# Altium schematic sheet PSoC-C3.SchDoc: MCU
size A3; CompanyName: Hitex GmbH; Address1: Greschbachstr. 12; Address2: 76229 Karlsruhe, Germany; Address3: www.hitex.com; DocumentNumber: 2; SheetNumber: 2; SheetTotal: 8; PageSetup: Record=PageOptions¦CenterHorizontal=True¦CenterVertical=True¦PrintScale=1.04¦XCorrection=1.00¦YCorrection=1.00¦PrintKind=0¦BorderSize=5000000¦LeftOffset=0¦BottomOffset=0¦Orientation=2¦PaperLength=1000¦PaperWidth=1000¦Scale=100¦PaperSource=7¦PrintQuality=1200¦MediaType=1¦DitherType=10¦PaperKind=A3¦PrintScaleMode=1
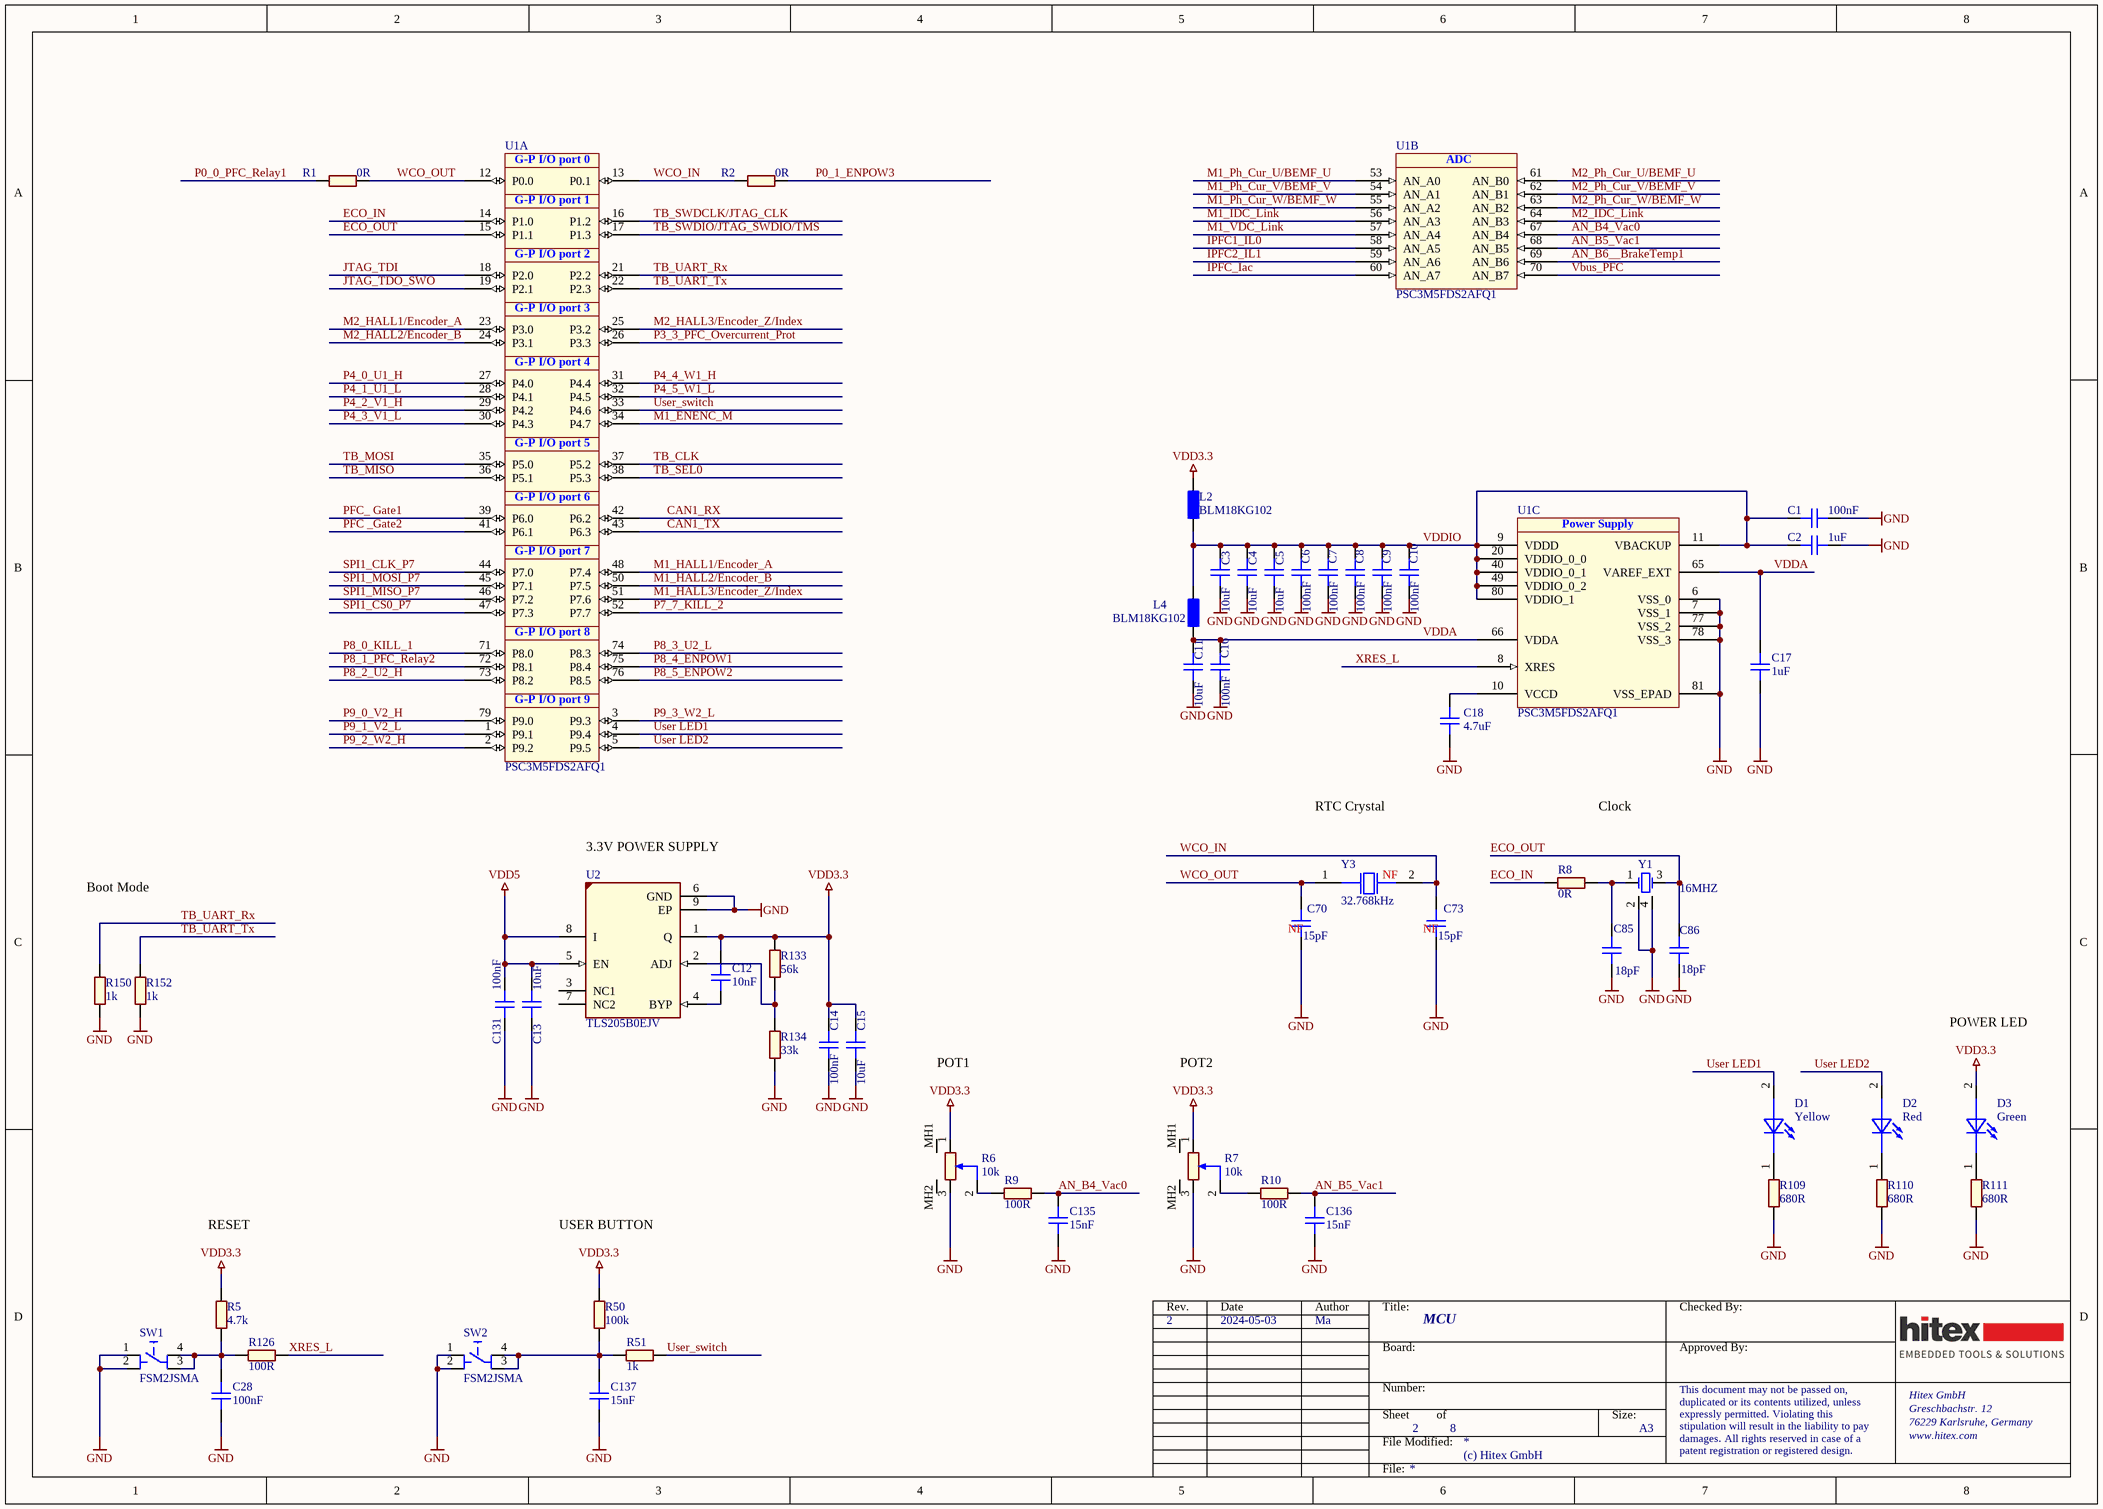
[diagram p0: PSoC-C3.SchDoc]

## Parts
C1  100nF  [CAPC1005X60N]
C2  1uF  [CAPC1608X90N-1]
C3  10uF  [CAPC3216X180N]
C4  10uF  [CAPC3216X180N]
C5  10uF  [CAPC3216X180N]
C6  100nF  [CAPC1005X60N]
C7  100nF  [CAPC1005X60N]
C8  100nF  [CAPC1005X60N]
C9  100nF  [CAPC1005X60N]
C10  100nF  [CAPC1005X60N]
C11  10uF  [CAPC3216X180N]
C12  10nF  [CAPC1005X55N-0]
C13  10uF  [CAPC3216X180N]
C14  100nF  [CAPC1005X60N]
C15  10uF  [CAPC3216X180N]
C16  100nF  [CAPC1005X60N]
C17  1uF  [CAPC1608X90N-1]
C18  4.7uF  [CAPC2013X145N-3]
C28  100nF  [CAPC1005X60N]
C70  15pF  [CAPC1005X55N-0]
C73  15pF  [CAPC1005X55N-0]
C85  18pF  [CAPC1005X55N-0]
C86  18pF  [CAPC1005X55N-0]
C131  100nF  [CAPC1005X55N-0]
C135  15nF  [CAPC1005X55N-0]
C136  15nF  [CAPC1005X55N-0]
C137  15nF  [CAPC1005X55N-0]
D1  Yellow  [LEDSC160X80X40-2N]
D2  Red  [LEDSC160X80X80-2N]
D3  Green  [LEDSC160X80X40-2N]
L2  BLM18KG102  [INDC1608N]
L4  BLM18KG102  [INDC1608N]
R1  0R  [RESC1005N]
R2  0R  [RESC1005N]
R5  4.7k  [RESC1609X50N]
R6  10k  [POT-THT-PTV09A-4020U]
R7  10k  [POT-THT-PTV09A-4020U]
R8  0R  [RESC1005X03N]
R9  100R  [RESC1005X40N-1]
R10  100R  [RESC1005X40N-1]
R50  100k  [RESC1005X40N]
R51  1k  [RESC1005X40N]
R109  680R  [RESC1608X55N-1]
R110  680R  [RESC1608X55N-1]
R111  680R  [RESC1608X55N-1]
R126  100R  [RESC1005X40N-1]
R133  56k  [RESC1005X40N]
R134  33k  [RESC1005X40N]
R150  1k  [RESC1005X40N]
R152  1k  [RESC1005X40N]
SW1  FSM2JSMA  [FSM2JSMA]
SW2  FSM2JSMA  [FSM2JSMA]
U1  PSC3M5FDS2AFQ1  [QFP50P1400X1400X160-81N]  (parts A,B,C of 3)
U2  TLS205B0EJV  [SOIC127P600X170-9N-3-V1]
Y1  16MHZ  [Oscillator_3225]
Y3  32.768kHz  [XTAL-SMD-ABS07]

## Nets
GND: C1.1 C2.1 C3.1 C4.1 C5.1 C6.1 C7.1 C8.1 C9.1 C10.1 C11.1 C13.1 C14.1 C15.1 C16.1 C17.1 C18.1 C28.1 C70.1 C73.1 C85.1 C86.1 C131.1 C135.2 C136.2 C137.2 R6.3 R7.3 R109.2 R110.2 R111.2 R134.1 R150.1 R152.1 SW1.1 SW1.2 SW2.1 SW2.2 U1.6(VSS_0) U1.7(VSS_1) U1.77(VSS_2) U1.78(VSS_3) U1.81(VSS_EPAD) U2.6(GND) U2.9(EP) Y1.2(GND) Y1.4(GND)
VDD3.3: C12.2 C14.2 C15.2 D3.2(Anode) L2.1 R5.2 R6.1 R7.1 R50.1 R133.2 U2.1(Q)
VDD5: C13.2 C131.2 U2.5(EN) U2.8(I)
AN_B4_Vac0: C135.1 R9.2 U1.67(AN_B4)
AN_B5_Vac1: C136.1 R10.2 U1.68(AN_B5)
AN_B6__BrakeTemp1: U1.69(AN_B6)
CAN1_RX: U1.42(P6.2)
CAN1_TX: U1.43(P6.3)
ECO_IN: R8.1 U1.14(P1.0)
ECO_OUT: C86.2 U1.15(P1.1) Y1.3(OSC2)
IPFC1_IL0: U1.58(AN_A5)
IPFC2_IL1: U1.59(AN_A6)
IPFC_Iac: U1.60(AN_A7)
JTAG_TDI: U1.18(P2.0)
JTAG_TDO_SWO: U1.19(P2.1)
M1_ENENC_M: U1.34(P4.7)
M1_HALL1/Encoder_A: U1.48(P7.4)
M1_HALL2/Encoder_B: U1.50(P7.5)
M1_HALL3/Encoder_Z/Index: U1.51(P7.6)
M1_IDC_Link: U1.56(AN_A3)
M1_Ph_Cur_U/BEMF_U: U1.53(AN_A0)
M1_Ph_Cur_V/BEMF_V: U1.54(AN_A1)
M1_Ph_Cur_W/BEMF_W: U1.55(AN_A2)
M1_VDC_Link: U1.57(AN_A4)
M2_HALL1/Encoder_A: U1.23(P3.0)
M2_HALL2/Encoder_B: U1.24(P3.1)
M2_HALL3/Encoder_Z/Index: U1.25(P3.2)
M2_IDC_Link: U1.64(AN_B3)
M2_Ph_Cur_U/BEMF_U: U1.61(AN_B0)
M2_Ph_Cur_V/BEMF_V: U1.62(AN_B1)
M2_Ph_Cur_W/BEMF_W: U1.63(AN_B2)
P0_0_PFC_Relay1: R1.1
P0_1_ENPOW3: R2.2
P3_3_PFC_Overcurrent_Prot: U1.26(P3.3)
P4_0_U1_H: U1.27(P4.0)
P4_1_U1_L: U1.28(P4.1)
P4_2_V1_H: U1.29(P4.2)
P4_3_V1_L: U1.30(P4.3)
P4_4_W1_H: U1.31(P4.4)
P4_5_W1_L: U1.32(P4.5)
P7_7_KILL_2: U1.52(P7.7)
P8_0_KILL_1: U1.71(P8.0)
P8_1_PFC_Relay2: U1.72(P8.1)
P8_2_U2_H: U1.73(P8.2)
P8_3_U2_L: U1.74(P8.3)
P8_4_ENPOW1: U1.75(P8.4)
P8_5_ENPOW2: U1.76(P8.5)
P9_0_V2_H: U1.79(P9.0)
P9_1_V2_L: U1.1(P9.1)
P9_2_W2_H: U1.2(P9.2)
P9_3_W2_L: U1.3(P9.3)
PFC _Gate2: U1.41(P6.1)
PFC_ Gate1: U1.39(P6.0)
SPI1_CLK_P7: U1.44(P7.0)
SPI1_CS0_P7: U1.47(P7.3)
SPI1_MISO_P7: U1.46(P7.2)
SPI1_MOSI_P7: U1.45(P7.1)
TB_CLK: U1.37(P5.2)
TB_MISO: U1.36(P5.1)
TB_MOSI: U1.35(P5.0)
TB_SEL0: U1.38(P5.3)
TB_SWDCLK/JTAG_CLK: U1.16(P1.2)
TB_SWDIO/JTAG_SWDIO/TMS: U1.17(P1.3)
TB_UART_Rx: R150.2 U1.21(P2.2)
TB_UART_Tx: R152.2 U1.22(P2.3)
User LED1: D1.2(Anode) U1.4(P9.4)
User LED2: D2.2(Anode) U1.5(P9.5)
User_switch: R51.2 U1.33(P4.6)
Vbus_PFC: U1.70(AN_B7)
VDDA: C11.2 C16.2 C17.2 L4.2 U1.65(VAREF_EXT) U1.66(VDDA)
VDDIO: C1.2 C2.2 C3.2 C4.2 C5.2 C6.2 C7.2 C8.2 C9.2 C10.2 L2.2 L4.1 U1.9(VDDD) U1.11(VBACKUP) U1.20(VDDIO_0_0) U1.40(VDDIO_0_1) U1.49(VDDIO_0_2) U1.80(VDDIO_1)
WCO_IN: C73.2 R2.1 U1.13(P0.1) Y3.2
WCO_OUT: C70.2 R1.2 U1.12(P0.0) Y3.1
XRES_L: R126.2 U1.8(XRES)
NetC12_1: C12.1 U2.4(BYP)
NetC18_2: C18.2 U1.10(VCCD)
NetC28_2: C28.2 R5.1 R126.1 SW1.3 SW1.4
NetC85_2: C85.2 R8.2 Y1.1(OSC1)
NetC137_1: C137.1 R50.2 R51.1 SW2.3 SW2.4
NetD1_1: D1.1(Cathode) R109.1
NetD2_1: D2.1(Cathode) R110.1
NetD3_1: D3.1(Cathode) R111.1
NetR6_2: R6.2 R9.1
NetR7_2: R7.2 R10.1
NetR133_1: R133.1 R134.2 U2.2(ADJ)

Not connected (* = marked no-connect by the designer): R6 MH1 MH2; R7 MH1 MH2; U2 3(NC1) 7(NC2)

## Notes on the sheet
- (near U2) 3.3V POWER SUPPLY
- RTC Crystal
- Clock
- Boot Mode
- (near Y3) NF
- (near C70) NF
- (near C73) NF
- POWER LED
- POT1
- POT2
- RESET
- USER BUTTON
- 2
- 2024-05-03
- Ma

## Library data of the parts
C1 C6-C10 C14 C16 C28 = 507459: CAP / CERA / 100nF / 50V / 10% / X7R (EIA) / -55°C to 125°C / 0402(1005) / SMD / -; Multiple Parts: No; Manufacturer: TDK Corporation; Manufacturer Order Number: C1005X7R1H104K050BE; Symbol Type: Capacitor; Single; Standard; 2 Pins; Alternate View: Yes; Article Number: 507459; Version Number: V01; Combined Parameters: TC:X7R (EIA);Tol.:-10%/+10%;Vdc:50V; QuickPick: 100nF / 50V / 10% / X7R (EIA) / 0402 (1005); Type: Standard; Style: Single; Package Metric: 1005; Package Imperial: 0402; ComponentStatus: Released; PLMStatus: Active; HTX: 01.22.0596.0
C2 C17 = 668123: CAP / CERA / 1uF / 25V / 10% / X7R (EIA) / -55°C to 125°C / 0603(1608) / SMD / -; Multiple Parts: No; Manufacturer: Samsung; Manufacturer Order Number: CL10B105KA8NNNC; Symbol Type: Capacitor; Single; Standard; 2 Pins; Alternate View: Yes; Article Number: 668123; Version Number: V01; Combined Parameters: TC:X7R (EIA);Tol.:-10%/+10%;Vdc:25V; QuickPick: 1uF / 25V / 10% / X7R (EIA) / 0603 (1608); Type: Standard; Style: Single; Package Metric: 1608; Package Imperial: 0603; ComponentStatus: Released; PLMStatus: Active; HTX: 01.22.0270.0
C3-C5 C11 C13 C15 = 282249: CAP / CERA / 10uF / 50V / 20% / X5R (EIA) / -55°C to 85°C / 1206(3216) / SMD / -; Multiple Parts: No; Manufacturer: MuRata; Manufacturer Order Number: GRM31CR61H106MA12L; Symbol Type: Capacitor; Single; Standard; 2 Pins; Alternate View: Yes; Article Number: 282249; Version Number: V01; Combined Parameters: TC:X5R (EIA);Tol.:-20%/+20%;Vdc:50V; QuickPick: 10uF / 50V / 20% / X5R (EIA) / 1206 (3216); Type: Standard; Style: Single; Package Metric: 3216; Package Imperial: 1206; ComponentStatus: Released; PLMStatus: Not Recommended For New Designs; HTX: 01.22.0647.0
C12 = 264563: CAP / CERA / 10nF / 16V / 5% / X7R (EIA) / -55°C to 125°C / 0402(1005) / SMD / -; Multiple Parts: No; Legacy PartNumber: CAP01001706; Manufacturer: MuRata; Manufacturer Order Number: GRM155R71C103JA01; Symbol Type: Capacitor; Single; Standard; 2 Pins; Alternate View: Yes; Article Number: 264563; Version Number: V01; Combined Parameters: TC:X7R (EIA);Tol.:-5%/+5%;Vdc:16V; QuickPick: 10nF / 16V / 5% / X7R (EIA) / 0402 (1005); Type: Standard; Style: Single; Package Metric: 1005; Package Imperial: 0402; ComponentStatus: Released; PLMStatus: Not Recommended For New Designs; HTX: 01.22.0592.0
C18 = 673682: CAP / CERA / 4.7uF / 25V / 20% / X7R (EIA) / -55°C to 125°C / 0805 / SMD / -; Multiple Parts: No; Manufacturer: Yageo; Manufacturer Order Number: CC0805MKX7R8BB475; Symbol Type: Capacitor; Single; Standard; 2 Pins; Alternate View: Yes; Article Number: 673682; Version Number: V00; Combined Parameters: TC:X7R (EIA);Tol.:-20%/+20%;Vdc:25V; QuickPick: 4.7uF / 25V / 20% / X7R (EIA) / 0805; Type: Standard; Style: Single; ComponentStatus: Released; PLMStatus: Active; HTX: 01.22.0436.0
C70 C73 = 287311: CAP / CERA / 15pF / 50V / 2% / C0G (EIA) / NP0 / -55°C to 125°C / 0402(1005) / SMD / -; Multiple Parts: No; Legacy PartNumber: CAP01006535; Manufacturer: MuRata; Manufacturer Order Number: GCM1555C1H150GA16; Symbol Type: Capacitor; Single; Standard; 2 Pins; Alternate View: Yes; Article Number: 287311; Version Number: V01; Combined Parameters: TC:C0G (EIA) / NP0;Tol.:-2%/+2%;Vdc:50V; QuickPick: 15pF / 50V / 2% / C0G (EIA) / NP0 / 0402 (1005); Type: Standard; Style: Single; Automotive Qualified: AEC Q200; Package Metric: 1005; Package Imperial: 0402; ComponentStatus: Released; PLMStatus: Active; HTX: 01.22.0669.0
C85 C86 = 287356: CAP / CERA / 18pF / 50V / 1% / C0G (EIA) / NP0 / -55°C to 125°C / 0402(1005) / SMD / -; Multiple Parts: No; Legacy PartNumber: CAP01006544; Manufacturer: MuRata; Manufacturer Order Number: GCM1555C1H180FA16; Symbol Type: Capacitor; Single; Standard; 2 Pins; Alternate View: Yes; Article Number: 287356; Version Number: V01; Combined Parameters: TC:C0G (EIA) / NP0;Tol.:-1%/+1%;Vdc:50V; QuickPick: 18pF / 50V / 1% / C0G (EIA) / NP0 / 0402 (1005); Type: Standard; Style: Single; Automotive Qualified: AEC Q200; Package Metric: 1005; Package Imperial: 0402; ComponentStatus: Released; PLMStatus: Active; HTX: 01.22.2169.0
C131 = 310625: CAP / CERA / 100nF / 50V / 10% / X7R (EIA) / -55°C to 125°C / 0402(1005) / SMD / -; Multiple Parts: No; Legacy PartNumber: CAP01010920; Manufacturer: MuRata; Manufacturer Order Number: GRM155R71H104KE14D; Symbol Type: Capacitor; Single; Standard; 2 Pins; Alternate View: Yes; Article Number: 310625; Version Number: V01; Combined Parameters: TC:X7R (EIA);Tol.:-10%/+10%;Vdc:50V; QuickPick: 100nF / 50V / 10% / X7R (EIA) / 0402 (1005M); Type: Standard; Style: Single; Package Metric: 1005; Package Imperial: 0402; ComponentStatus: Released; PLMStatus: Active; HTX: 01.22.0596.0
C135-C137 = 289336: CAP / CERA / 15nF / 50V / 20% / X7R (EIA) / -55°C to 125°C / 0402(1005) / SMD / -; Multiple Parts: No; Legacy PartNumber: CAP01006940; Manufacturer: MuRata; Manufacturer Order Number: GCM155R71H153MA55; Symbol Type: Capacitor; Single; Standard; 2 Pins; Alternate View: Yes; Article Number: 289336; Version Number: V01; Combined Parameters: TC:X7R (EIA);Tol.:-20%/+20%;Vdc:50V; QuickPick: 15nF / 50V / 20% / X7R (EIA) / 0402 (1005); Type: Standard; Style: Single; Automotive Qualified: AEC Q200; Package Metric: 1005; Package Imperial: 0402; ComponentStatus: Released; PLMStatus: Active; HTX: 01.22.0662.0
D1 = 678278: Chip LED, 589nm, Yellow, Electronic Equipment Applications; Manufacturer: OSRAM Opto Semiconductors; Manufacturer Order Number: LY Q396-P1Q2-36; Symbol Type: Standard LED Symbol, 1 Cathode, 2 Anode; Article Number: 678278; Version Number: V01; Combined Parameters: Vf:2.3V;If:20mA;Ur:12V;Ir:10uA;Pmax:-; QuickPick: LED / 0603; Style: Single; Automotive Qualified: No; ComponentStatus: Released; PLMStatus: Active; Second Source allowed: Yes; Voltage DC (max): na; HTX: 00.96.0115.0
D2 = 494911: ChipLED 0603, Red, 633nm, Temp Raneg(-30 to 85°C); Manufacturer: OSRAM Opto Semiconductors; Manufacturer Order Number: LSQ971-Z; Symbol Type: Standard LED Symbol, 1 Cathode, 2 Anode; Article Number: 494911; Version Number: V01; Combined Parameters: Vf:2.5V;If:25mA;Ur:12V;Ir:10uA;Pmax:-; QuickPick: LED / 603; Type: LED; Style: Single; Automotive Qualified: No; ComponentStatus: Released; PLMStatus: Active; Second Source allowed: Yes; Voltage DC (max): na; HTX: 00.96.0114.0
D3 = 678273: Chip LED, 573nm, Green, Electronic Equipment Applications; Manufacturer: OSRAM Opto Semiconductors; Manufacturer Order Number: LG Q396-PS-35; Symbol Type: Standard LED Symbol, 1 Cathode, 2 Anode; Article Number: 678273; Version Number: V00; Combined Parameters: Vf:2.4V;If:30mA;Ur:12V;Ir:10uA;Pmax:-; QuickPick: LED / 0603; Style: Single; Automotive Qualified: No; ComponentStatus: Released; PLMStatus: Active; Second Source allowed: Yes; Voltage DC (max): na; HTX: 00.96.0122.0
L2 L4 = BLM18KG102SN1D: FERRITE, SMD, 1000 OHM, 0.8A, 0603; PartNumber: 01.30.0521.0; Manufacturer: Murata; Designer: Th; CheckOrientation: false
R1 R2 = Solderbridge_2Pad_0R_0402: SMD solderbridge, 2 Pads, 0R resistor populated, 0402 size; PartNumber: 01.02.0902.0; Designer: Ma; CheckOrientation: false
R5 = 345982: RES / STD / 4.7k / 100mW / 1% / 100ppm/K / -55°C to 155°C / 0603(1608) / SMD / -; Multiple Parts: No; Legacy PartNumber: RES01801219; Manufacturer: Vishay; Manufacturer Order Number: CRCW06034K70FK; Symbol Type: Resistor; Single; Standard; 2 Pins; Alternate View: Yes; Article Number: 345982; Version Number: V01; Combined Parameters: TCR:100ppm/K;Tol.:-1%/+1%;Vdc:75V;Idc:-;P:100mW; QuickPick: 4.7k / 1% / 0.1 / 0603 (1608); Style: Single; Automotive Qualified: AEC Q200; Package Metric: 1608; Package Imperial: 0603; ComponentStatus: Released; PLMStatus: Active; Voltage DC (max): 75V; HTX: 01.02.0437.0
R6 R7 = 675198: RES / VAR / 10k / 50mW / 20% / - / -10°C to 50°C /  THT, 2.5 mm pitch, 11.80 mm L X 10 mm W X 20.5 mm H body / - / -; Multiple Parts: No; Manufacturer: Bourns; Manufacturer Order Number: PTV09A-4020U-B103; Alternate View: Yes; Symbol Type: Resistor; Single; Variable; 3 Pins; Article Number: 675198; Version Number: V01; Combined Parameters: TCR:-;Tol.:-20%/+20%;Vdc:20V;Idc:-;P:50mW; QuickPick: 10k / 20% / 0.05 / Horizontal/Rear Mount w/Sleeve Bushing; Style: Single; ComponentStatus: Released; PLMStatus: Active; Voltage DC (max): 20V; HTX: 01.04.0034.0
R8 = 327372: RES / STD / 0R / 63mW / 0R / 0ppm/K / -55°C to 155°C / 0402(1005) / SMD / -; Multiple Parts: No; Legacy PartNumber: RES00000001; Manufacturer: Yageo; Manufacturer Order Number: RC0402JR-070RL; Symbol Type: Resistor; Single; Standard; 2 Pins; Alternate View: Yes; Article Number: 327372; Version Number: V01; Combined Parameters: TCR:0ppm/K;Tol.:-0R/+0R;Vdc:50V;Idc:1A;P:63mW; QuickPick: 0R / 0R / 0.063 / 0402 (1005); Style: Single; Package Metric: 1005; Package Imperial: 0402; ComponentStatus: Released; PLMStatus: Active; Voltage DC (max): 50V; HTX: 01.02.0902.0
R9 R10 R126 = 327441: RES / STD / 100R / 63mW / 1% / 100ppm/K / -55°C to 155°C / 0402(1005) / SMD / -; Multiple Parts: No; Manufacturer: Yageo; Manufacturer Order Number: RC0402FR-07100RL; Symbol Type: Resistor; Single; Standard; 2 Pins; Alternate View: Yes; Article Number: 327441; Version Number: V00; Combined Parameters: TCR:100ppm/K;Tol.:-1%/+1%;Vdc:-;Idc:-;P:63mW; QuickPick: 100R / 1% / 0.063 / 0402 (1005); Style: Single; Package Metric: 1005; Package Imperial: 0402; ComponentStatus: Released; PLMStatus: Active; HTX: 01.02.1130.0
R50 = 342737: RES / STD / 100k / 63mW / 1% / 100ppm/K / -55°C to 155°C / 0402 / SMD / -; Multiple Parts: No; Legacy PartNumber: RES01800571; Manufacturer: Vishay; Manufacturer Order Number: CRCW0402100KFK; Symbol Type: Resistor; Single; Standard; 2 Pins; Alternate View: Yes; Article Number: 342737; Version Number: V01; Combined Parameters: TCR:100ppm/K;Tol.:-1%/+1%;Vdc:50V;Idc:-;P:63mW; QuickPick: 100k / 1% / 0.063 / 0402; Style: Single; Automotive Qualified: AEC Q200; ComponentStatus: Released; PLMStatus: Active; Voltage DC (max): 50V; HTX: 01.02.0716.0
R51 R150 R152 = 341597: RES / STD / 1k / 63mW / 1% / 100ppm/K / -55°C to 155°C / 0402(1005) / SMD / -; Multiple Parts: No; Legacy PartNumber: RES01800343; Manufacturer: Vishay; Manufacturer Order Number: CRCW04021K00FK; Symbol Type: Resistor; Single; Standard; 2 Pins; Alternate View: Yes; Article Number: 341597; Version Number: V01; Combined Parameters: TCR:100ppm/K;Tol.:-1%/+1%;Vdc:50V;Idc:-;P:63mW; QuickPick: 1k / 1% / 0.063 / 0402 (1005); Style: Single; Automotive Qualified: AEC Q200; Package Metric: 1005; Package Imperial: 0402; ComponentStatus: Released; PLMStatus: Active; Voltage DC (max): 50V; HTX: 01.02.0701.0
R109-R111 = 330423: RES / STD / 680R / 100mW / 1% / 100ppm/K / -55°C to 155°C / 0603(1608) / SMD / -; Multiple Parts: No; Manufacturer: Yageo; Manufacturer Order Number: AC0603FR-07680RL; Symbol Type: Resistor; Single; Standard; 2 Pins; Alternate View: Yes; Article Number: 330423; Version Number: V01; Combined Parameters: TCR:100ppm/K;Tol.:-1%/+1%;Vdc:75V;Idc:-;P:100mW; QuickPick: 680R / 1% / 0.1 / 0603 (1608); Style: Single; Automotive Qualified: AEC Q200; Package Metric: 1608; Package Imperial: 0603; ComponentStatus: Released; PLMStatus: Active; Voltage DC (max): 75V; HTX: 01.02.0464.0
R133 = 342592: RES / STD / 56k / 63mW / 1% / 100ppm/K / -55°C to 155°C / 0402(1005) / SMD / -; Multiple Parts: No; Legacy PartNumber: RES01800542; Manufacturer: Vishay; Manufacturer Order Number: CRCW040256K0FK; Symbol Type: Resistor; Single; Standard; 2 Pins; Alternate View: Yes; Article Number: 342592; Version Number: V01; Combined Parameters: TCR:100ppm/K;Tol.:-1%/+1%;Vdc:50V;Idc:-;P:63mW; QuickPick: 56k / 1% / 0.063 / 0402 (1005); Style: Single; Automotive Qualified: AEC Q200; Package Metric: 1005; Package Imperial: 0402; ComponentStatus: Released; PLMStatus: Active; Voltage DC (max): 50V; HTX: 01.02.0770.0
R134 = 342452: RES / STD / 33k / 63mW / 1% / 100ppm/K / -55°C to 155°C / 0402(1005) / SMD / -; Multiple Parts: No; Legacy PartNumber: RES01800514; Manufacturer: Vishay; Manufacturer Order Number: CRCW040233K0FK; Symbol Type: Resistor; Single; Standard; 2 Pins; Alternate View: Yes; Article Number: 342452; Version Number: V01; Combined Parameters: TCR:100ppm/K;Tol.:-1%/+1%;Vdc:50V;Idc:-;P:63mW; QuickPick: 33k / 1% / 0.063 / 0402 (1005); Style: Single; Automotive Qualified: AEC Q200; Package Metric: 1005; Package Imperial: 0402; ComponentStatus: Released; PLMStatus: Active; Voltage DC (max): 50V; HTX: 01.02.0765.0
SW1 SW2 = 376475: Micro Miniature Pushbutton Switch; Legacy PartNumber: SW0000003; Manufacturer: Tyco Electronics; Article Number: 376475; Version Number: V01; Legacy DeviceID: TEC_FSM2JSMA; Style: Not Applicable; Automotive Qualified: No; ComponentStatus: Released; PLMStatus: Active; Second Source allowed: Yes; Voltage DC (max): na; HTX: 03.00.0066.0
U1 = PSC3M5FDS2AFQ1: PSoC C3 Main Line, Cortex-M33, 180 MHz, 64KB SRAM, 256KB Flash, E-LQFP-80; Manufacturer: Infineon Technologies AG; Designer: Kr; CheckOrientation: true; HTX: 00.80.0834.0
U2 = 592428: Micropower, low noise, low dropout voltage regulator, Designed for use in battery-powered systems, the low quiescent current of 30 µA makes it an ideal choice; Multiple Parts: No; Manufacturer: Infineon Technologies; Symbol Type: Low Dropout, Low Noise, Linear Voltage Post Regulator, 3.3V, 500 mA; Article Number: 592428; Version Number: V01; Legacy DeviceID: IFX_TLS205B0EJV; Combined Parameters: Linear - -;Vo:1.19V to 1.25V; QuickPick: Linear / PG-DSO-8-52; Automotive Qualified: Yes; ComponentStatus: Released; PLMStatus: Active; Voltage DC (max): na; HTX: 00.40.0359.0
Y1 = 16MHz/3225/4PAD: 16MHz 8pF 50ppm/15ppm; PartNumber: 00.98.0120.0; Manufacturer: NDK; ManufacturerPartNo: NX3225SA 16MHZ AT-W; Designer: Ar; CheckOrientation: true
Y3 = 409415: SMD Low Profile Crystal, 32.768kHz, Load Capacitance 12.5 pF (Operating Temp -40°C to +85°C); Legacy PartNumber: IC02600599; Manufacturer: Abracon Corporation; Manufacturer Order Number: ABS07-32.768kHz; Symbol type: Standard Crystal Symbol, 2 Pins; Article Number: 409415; Version Number: V01; Legacy DeviceID: ABR_ABS07-32.768kHz; Tolerance Neg: 20%; Combined Parameters: Standard Standard Crystal;Tol.:-20%/+20%; QuickPick: 32768 / Crystal; Style: Standard; Automotive Qualified: No; ComponentStatus: Released; PLMStatus: Active; Second Source allowed: Yes; Voltage DC (max): na; HTX: 01.17.0046.0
